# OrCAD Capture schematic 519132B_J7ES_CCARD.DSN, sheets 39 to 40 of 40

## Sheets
39 37.EXPANSION/GNSS: size C; rev: A
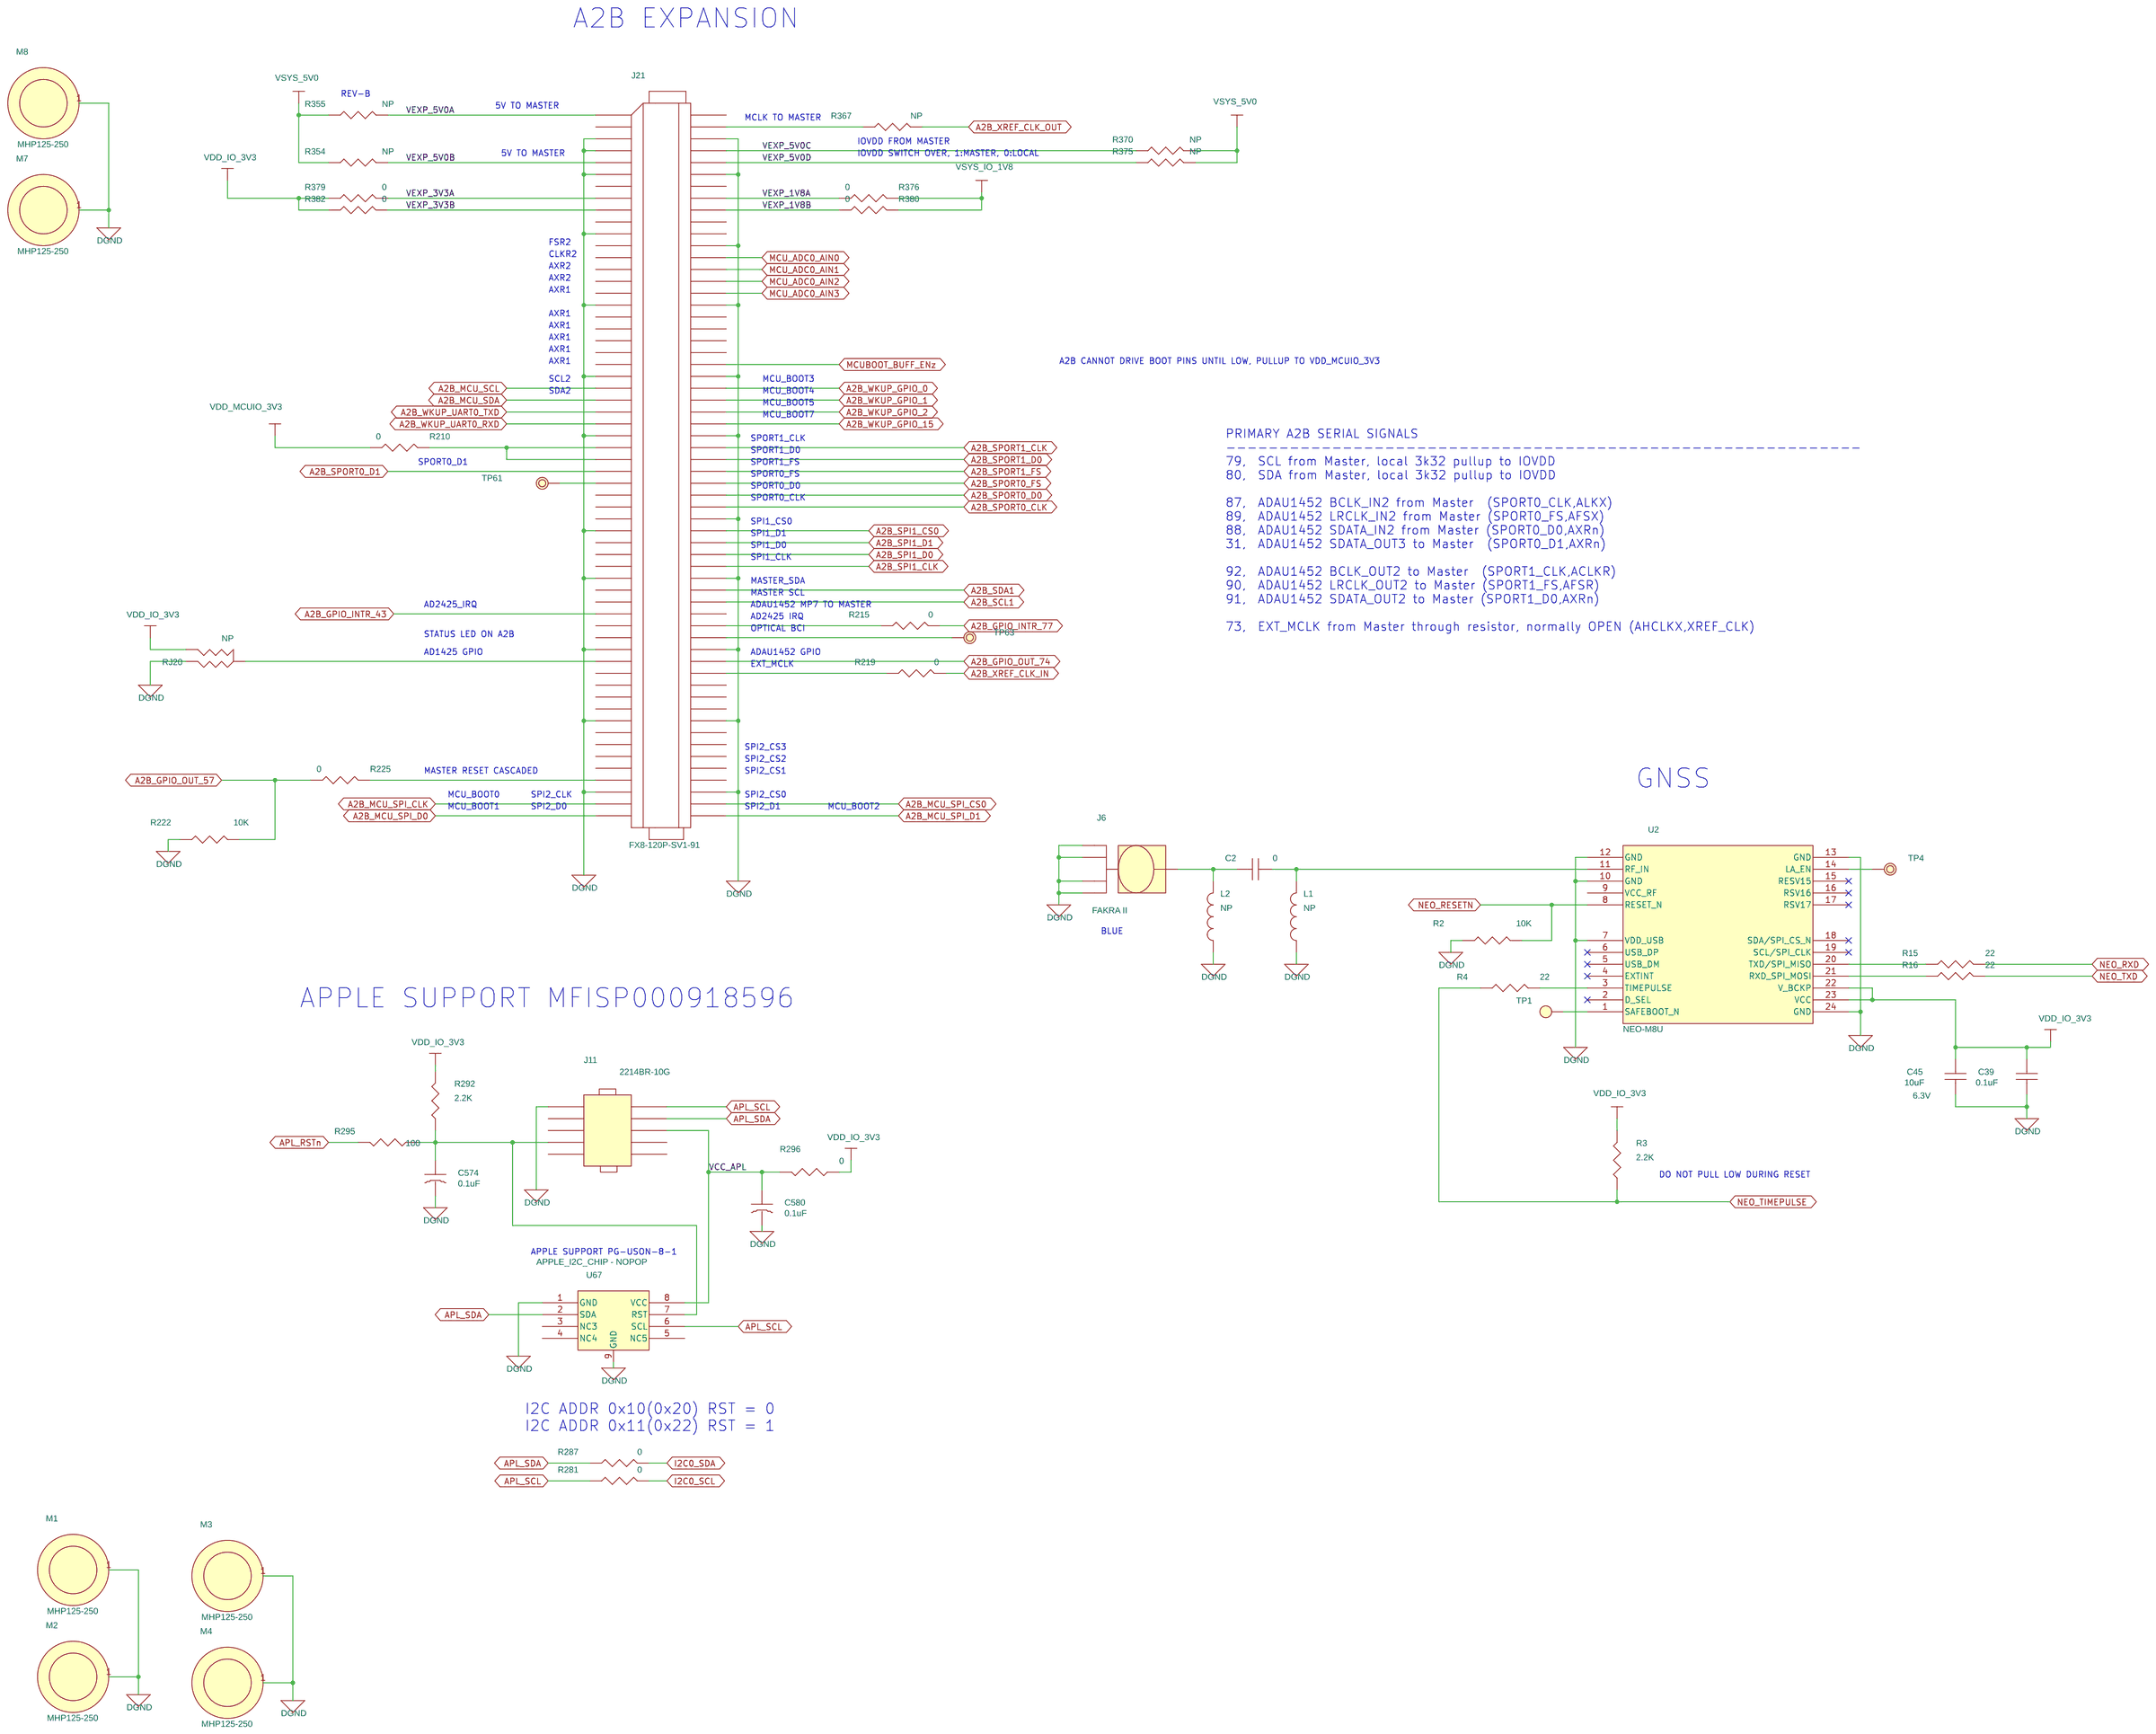
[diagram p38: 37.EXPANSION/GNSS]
40 26.SECONDARY LDO'S/SWITCHES: size C; rev: A
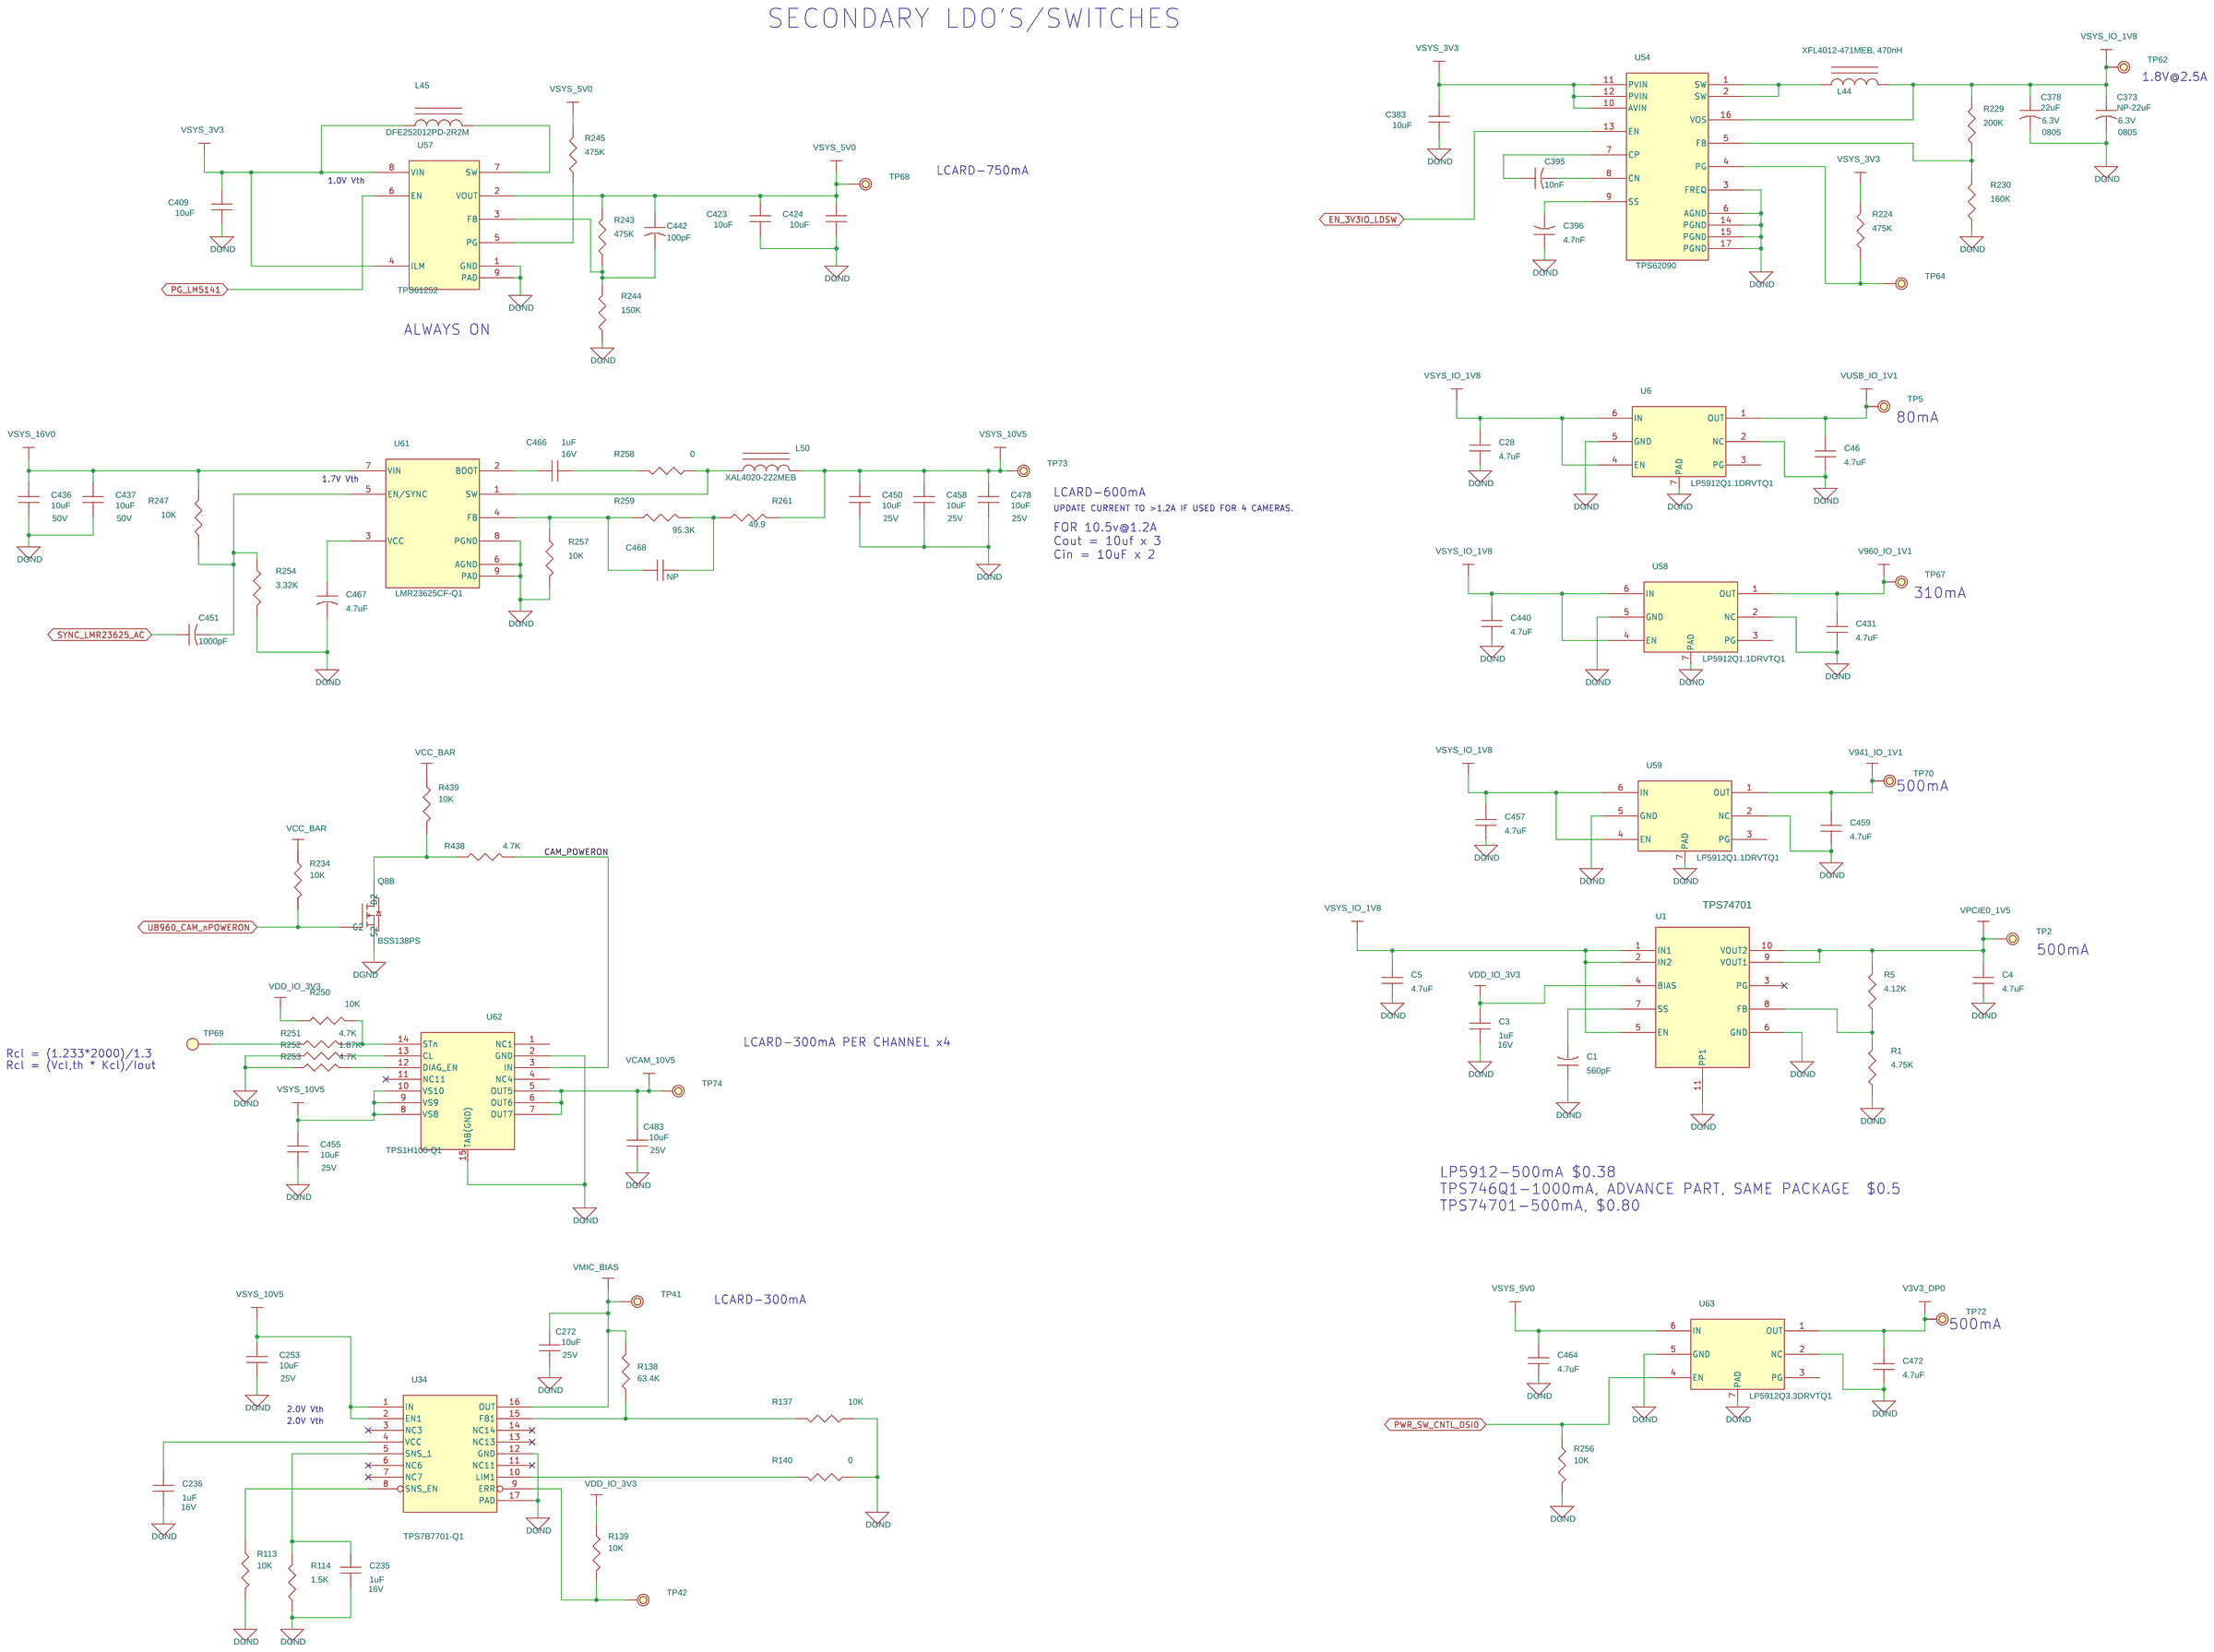
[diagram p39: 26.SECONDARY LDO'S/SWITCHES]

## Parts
sheet 14. SOC MCU & MAIN GEN IO, OSC
Q8  BSS138PS  [sot363-16x45]  (sections A,B)
sheet 26.SECONDARY LDO'S/SWITCHES
C1  560pF  [c402-25]
C3  1uF  [c603-35x45]
C4  4.7uF  [c805-35x60]
C5  4.7uF  [c805-35x60]
C28  4.7uF  [c805-35x60]
C46  4.7uF  [c805-35x60]
C235  1uF  [c603-35x45]
C236  1uF  [c603-35x45]
C253  10uF  [C1206-40X70]
C272  10uF  [C1206-40X70]
C373  NP-22uF  [c805-35x60]
C378  22uF  [c805-35x60]
C383  10uF  [c805-35x60]
C395  10nF  [c402-25]
C396  4.7nF  [c402-25]
C409  10uF  [c805-35x60]
C423  10uF  [c805-35x60]
C424  10uF  [c805-35x60]
C431  4.7uF  [c805-35x60]
C436  10uF  [c1210-70x102]
C437  10uF  [c1210-70x102]
C440  4.7uF  [c805-35x60]
C442  100pF  [c402-25]
C450  10uF  [C1206-40X70]
C451  1000pF  [c402-25]
C455  10uF  [C1206-40X70]
C457  4.7uF  [c805-35x60]
C458  10uF  [C1206-40X70]
C459  4.7uF  [c805-35x60]
C464  4.7uF  [c805-35x60]
C466  1uF  [c603-35x45]
C467  4.7uF  [c603-35x45]
C468  NP  [c402-25]
C472  4.7uF  [c805-35x60]
C478  10uF  [C1206-40X70]
C483  10uF  [C1206-40X70]
L44  XFL4012-471MEB, 470nH  [coil-xlf4012]
L45  DFE252012PD-2R2M  [ind2520-40x80]
L50  XAL4020-222MEB  [coil-xal40]
R1  4.75K  [r402-25]
R5  4.12K  [r402-25]
R113  10K  [r402-25]
R114  1.5K  [r402-25]
R137  10K  [r402-25]
R138  63.4K  [r402-25]
R139  10K  [r402-25]
R140  0  [r402-25]
R224  475K  [r402-25]
R229  200K  [r402-25]
R230  160K  [r402-25]
R234  10K  [r402-25]
R243  475K  [r402-25]
R244  150K  [r402-25]
R245  475K  [r402-25]
R247  10K  [r402-25]
R250  10K  [r402-25]
R251  4.7K  [r402-25]
R252  1.87K  [r603-35x45]
R253  4.7K  [r402-25]
R254  3.32K  [r402-25]
R256  10K  [r402-25]
R257  10K  [r402-25]
R258  0  [r402-25]
R259  95.3K  [r402-25]
R261  49.9  [r402-25]
R438  4.7K  [r402-25]
R439  10K  [r402-25]
TP2  TP  [tp-30RD13]
TP5  TP  [tp-30RD13]
TP41  TP  [tp-30RD13]
TP42  TP  [tp-30RD13]
TP62  TP  [tp-30RD13]
TP64  TP  [tp-30RD13]
TP67  TP  [tp-30RD13]
TP68  TP  [tp-30RD13]
TP69  NP  [tp20]
TP70  TP  [tp-30RD13]
TP72  TP  [tp-30RD13]
TP73  TP  [tp-30RD13]
TP74  TP  [tp-30RD13]
U1  TPS74701  [drc10-11x33]
U6  LP5912Q1.1DRVTQ1  [drv6-12x30]
U34  TPS7B7701-Q1  [pwp16-14x70-pad]
U54  TPS62090  [rgt16-12x34]
U57  TPS61252  [dsg8-11x20]
U58  LP5912Q1.1DRVTQ1  [drv6-12x30]
U59  LP5912Q1.1DRVTQ1  [drv6-12x30]
U61  LMR23625CF-Q1  [DDA8-PAD]
U62  TPS1H100-Q1  [pwp14-14x70-pad]
U63  LP5912Q3.3DRVTQ1  [drv6-12x30]
sheet 37.EXPANSION/GNSS
C2  0  [c402-25]
C39  0.1uF  [c402-25]
C45  10uF  [c805-35x60]
C574  0.1uF  [c402-25]
C580  0.1uF  [c402-25]
J6  FAKRA II  [conn-st-fakra]
J11  2214BR-10G  [CON-2214BR-10G]
J21  FX8-120P-SV1-91  [FX8-120P-SV1]
L1  NP  [l402-25]
L2  NP  [l402-25]
M1  MHP125-250  [MHP125-250]
M2  MHP125-250  [MHP125-250]
M3  MHP125-250  [MHP125-250]
M4  MHP125-250  [MHP125-250]
M7  MHP125-250  [MHP125-250]
M8  MHP125-250  [MHP125-250]
R2  10K  [r402-25]
R3  2.2K  [r402-25]
R4  22  [r402-25]
R15  22  [r402-25]
R16  22  [r402-25]
R210  0  [r402-25]
R215  0  [r402-25]
R219  0  [r402-25]
R222  10K  [r402-25]
R225  0  [r402-25]
R281  0  [r402-25]
R287  0  [r402-25]
R292  2.2K  [r402-25]
R295  100  [r402-25]
R296  0  [r402-25]
R354  NP  [r402-25]
R355  NP  [r402-25]
R367  NP  [r402-25]
R370  NP  [r402-25]
R375  NP  [r402-25]
R376  0  [r402-25]
R379  0  [r402-25]
R380  0  [r402-25]
R382  0  [r402-25]
RJ20  NP  [JMP402-25]
TP1  TP  [TP20]
TP4  TP  [tp-30RD13]
TP61  TP  [tp-30RD13]
TP63  TP  [tp-30RD13]
U2  NEO-M8U  [NEO-M8U]
U67  APPLE_I2C_CHIP - NOPOP  [IC8-CP-USON]

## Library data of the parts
Q8 = BSS138PS: Part #: 104958-0001R
C1 = CAP: CAP CERAMIC 0.01uF 50V 10% X7R 0402; Chkd/date: SHREESHAIL/301105; Crtd /date: MAZHAR/040505; Custom_Duty: 15%; Customs_HS_Code: 85322990; Distributor_name: DIGIKEY; Distributor_part_number: 399-3066-1-ND; Footprint Path: Y:\MIS_DATABASE\Library\ALTIUM_TOOL\PCB_FOOTPRINTS\Altium_Footprint_Lib.PcbLib; Height: 0.55MM; Library Path: Y:\MIS_DATABASE\Library\ALTIUM_TOOL\SCHEMATICS_PARTS\MS_DISCRETE_Library.schlib; Mfr_name: KEMET; Mfr_part_number: C0402C103K5RACTU; Mistral Part No: 120009030025-R; Package: 0402; Part #: 101587-5601R; Part_type: CAPACITORS\CERAMIC; Project: G4_SVGA; RoHS: RoHS; Temperature: -55°C+125°C; Tolerance: 10%; Voltage: 50V; Wattage: NA; Weight: 0.65mg; Datasheet: Y:\MIS_DATABASE\DATASHEETS\CAPACITORS\KEMET-C-X7R.PDF
C3 C235 C236 = CAP_NP_0: Part #: 104723-0100R; Voltage: 16V
C4 C5 C28 C46 C431 C440 C457 C459 C464 C472 = CAP_AM_0805_4.7uf_x7r_16v_10_X: Part #: 104719-0470R
C253 C272 C450 C455 C458 C478 C483 = CAP_NP_0: Part #: 104724-0101R; Voltage: 25V
C373 = CAP: CAP CERAMIC 22uF 6.3V 20% X7T AUTO 0805; Chkd/date: MANIRAJA/261018; Crtd /date: ALVY/251018; Custom_Duty: 15%; Customs_HS_Code: 85322990; Distributor_name: MOUSER; Distributor_part_number: 81-GCM21BD70J226ME6L; Footprint Path: Y:\MIS_DATABASE\Library\ALTIUM_TOOL\PCB_FOOTPRINTS\Altium_Footprint_Lib.PcbLib; Height: 1.25MM; Library Path: Y:\MIS_DATABASE\Library\ALTIUM_TOOL\SCHEMATICS_PARTS\MS_DISCRETE_Library.schlib; Mfr_name: MURATA; Mfr_part_number: GCM21BD70J226ME36L; Mistral Part No: 120018100065-R; Package: 0805; Part #: C0805-NOPOP; Part_type: CAPACITORS\CERAMIC; Project: TI_J7ES_EVM_SOM; RoHS: RoHS; Temperature: -55°C+125°C; Tolerance: 20%; Voltage: 6.3V; Wattage: NA; Weight: NA; Datasheet: Y:\MIS_DATABASE\DATASHEETS\CAPACITORS\GCM-SERIES.PDF
C378 = CAP: CAP CERAMIC 22uF 6.3V 20% X7T AUTO 0805; Chkd/date: MANIRAJA/261018; Crtd /date: ALVY/251018; Custom_Duty: 15%; Customs_HS_Code: 85322990; Distributor_name: MOUSER; Distributor_part_number: 81-GCM21BD70J226ME6L; Footprint Path: Y:\MIS_DATABASE\Library\ALTIUM_TOOL\PCB_FOOTPRINTS\Altium_Footprint_Lib.PcbLib; Height: 1.25MM; Library Path: Y:\MIS_DATABASE\Library\ALTIUM_TOOL\SCHEMATICS_PARTS\MS_DISCRETE_Library.schlib; Mfr_name: MURATA; Mfr_part_number: GCM21BD70J226ME36L; Mistral Part No: 120018100065-R; Package: 0805; Part #: 105333-0221R; Part_type: CAPACITORS\CERAMIC; Project: TI_J7ES_EVM_SOM; RoHS: RoHS; Temperature: -55°C+125°C; Tolerance: 20%; Voltage: 6.3V; Wattage: NA; Weight: NA; Datasheet: Y:\MIS_DATABASE\DATASHEETS\CAPACITORS\GCM-SERIES.PDF
C383 C409 C423 C424 = CAP_AM_0805_10uf_x7r_10v_10_X: Part #: 104720-0101R
C395 = CAP: CAP CERAMIC 0.01uF 50V 10% X7R 0402; Chkd/date: SHREESHAIL/301105; Crtd /date: MAZHAR/040505; Custom_Duty: 15%; Customs_HS_Code: 85322990; Distributor_name: DIGIKEY; Distributor_part_number: 399-3066-1-ND; Footprint Path: Y:\MIS_DATABASE\Library\ALTIUM_TOOL\PCB_FOOTPRINTS\Altium_Footprint_Lib.PcbLib; Height: 0.55MM; Library Path: Y:\MIS_DATABASE\Library\ALTIUM_TOOL\SCHEMATICS_PARTS\MS_DISCRETE_Library.schlib; Mfr_name: KEMET; Mfr_part_number: C0402C103K5RACTU; Mistral Part No: 120009030025-R; Package: 0402; Part #: 104725-1101R; Part_type: CAPACITORS\CERAMIC; Project: G4_SVGA; RoHS: RoHS; Temperature: -55°C+125°C; Tolerance: 10%; Voltage: 50V; Wattage: NA; Weight: 0.65mg; Datasheet: Y:\MIS_DATABASE\DATASHEETS\CAPACITORS\KEMET-C-X7R.PDF
C396 = CAP: CAP CERAMIC 0.01uF 50V 10% X7R 0402; Chkd/date: SHREESHAIL/301105; Crtd /date: MAZHAR/040505; Custom_Duty: 15%; Customs_HS_Code: 85322990; Distributor_name: DIGIKEY; Distributor_part_number: 399-3066-1-ND; Footprint Path: Y:\MIS_DATABASE\Library\ALTIUM_TOOL\PCB_FOOTPRINTS\Altium_Footprint_Lib.PcbLib; Height: 0.55MM; Library Path: Y:\MIS_DATABASE\Library\ALTIUM_TOOL\SCHEMATICS_PARTS\MS_DISCRETE_Library.schlib; Mfr_name: KEMET; Mfr_part_number: C0402C103K5RACTU; Mistral Part No: 120009030025-R; Package: 0402; Part #: 103217-1472R; Part_type: CAPACITORS\CERAMIC; Project: G4_SVGA; RoHS: RoHS; Temperature: -55°C+125°C; Tolerance: 10%; Voltage: 25V; Wattage: NA; Weight: 0.65mg; Datasheet: Y:\MIS_DATABASE\DATASHEETS\CAPACITORS\KEMET-C-X7R.PDF
C436 C437 = CAP_NP_0: Part #: 104665-0101R; Voltage: 50V
C442 = CAP: Part #: 101782-1103R; Voltage: 50V
C451 = CAP: CAP CERAMIC 0.01uF 50V 10% X7R 0402; Chkd/date: SHREESHAIL/301105; Crtd /date: MAZHAR/040505; Custom_Duty: 15%; Customs_HS_Code: 85322990; Distributor_name: DIGIKEY; Distributor_part_number: 399-3066-1-ND; Footprint Path: Y:\MIS_DATABASE\Library\ALTIUM_TOOL\PCB_FOOTPRINTS\Altium_Footprint_Lib.PcbLib; Height: 0.55MM; Library Path: Y:\MIS_DATABASE\Library\ALTIUM_TOOL\SCHEMATICS_PARTS\MS_DISCRETE_Library.schlib; Mfr_name: KEMET; Mfr_part_number: C0402C103K5RACTU; Mistral Part No: 120009030025-R; Package: 0402; Part #: 102058-1102R; Part_type: CAPACITORS\CERAMIC; Project: G4_SVGA; RoHS: RoHS; Temperature: -55°C+125°C; Tolerance: 10%; Voltage: 50V; Wattage: NA; Weight: 0.65mg; Datasheet: Y:\MIS_DATABASE\DATASHEETS\CAPACITORS\KEMET-C-X7R.PDF
C466 = CAP_AM_0603_0.47uf_x7r_16v_10_X: Part #: 104723-0100R; Voltage: 16V
C467 = CAP: Part #: 104938-0470R; Voltage: 6.3V
C468 = CAP_AM_0402_0.1uf_x7r_16v_10%_X: Part #: C0402-NOPOP; Voltage: 50V
L44 = INDUCTOR_IRON: Part #: 105285-1470R
L45 = INDUCTOR_IRON: Part #: 104717-0220R
L50 = INDUCTOR_IRON: Part #: 104872-0220R
R1 = R: Part #: 102145-4752R
R5 = R: Part #: 102145-4122R
R2 R113 R137 R139 R222 R234 R247 R256 R439 = R: Part #: 102145-1003R
R114 = R: Part #: 102145-1502R
R138 = R: Part #: 102145-6343R
R140 R210 R215 R219 R225 R258 R281 R287 R296 R376 R379 R380 R382 = R: Part #: 101370-0001R
R224 R243 R245 = R: Part #: 102145-4754R
R229 = R: Part #: 102145-2004R
R230 = R: Part #: 102145-1604R
R244 = R: Part #: 102145-1504R
R250 = R_1: Part #: 102145-1003R
R251 R253 R438 = R_2: Part #: 102145-4702R
R252 = R_2: Part #: 100642-1872R
R254 = R: Part #: 102145-3322R
R257 = RESISTOR: Part #: 102145-1003R
R259 = RESISTOR: Part #: 102145-9533R
R261 = RESISTOR: Part #: 102145-4990R
TP2 TP4 TP5 TP41 TP42 TP61-TP64 TP67 TP68 TP70 TP72-TP74 = TP-30RD13: Part #: TP-30RD13-NO-POP
TP1 TP69 = TESTPOINT: Part #: SMT-TP020
U1 = U-TPS78601_AJUST_-_1_3.5A_LDO: Part #: 102752-0001R
U6 U58 U59 = LP5912-Q1: Part #: 105194-0011R
U34 = TPS7B7701-Q1: Part #: 104921-0001R
U54 = TPS62090: Part #: 105344-0001R
U57 = TPS61252: Part #: 104960-0001R
U61 = LMR23625CF-Q1: Part #: 104967-0001R
U62 = tps1h100-q1: Part #: 104666-0001R
U63 = LP5912-Q1: Part #: 105194-0033R
C2 = CAP_NP_3: Alternate_mfr_part_number_B: 102366-1685R; Part #: 101370-0001R
C39 = CAP_AM_0402_0.1uf_x7r_16v_10%_X: Part #: 104446-1100R
C45 = CAP_AM_0805_4.7uf_x7r_16v_10_X: Part #: 104936-0101R; Voltage: 6.3V
C574 C580 = CAP: Part #: 104446-1100R; Voltage: 16V
J6 = 59S20X-400L5-Z: Part #: 104894-0003R
J11 = HEADER_5X2: Part #: 105017-0010R
J21 = FX8-120P-SV1-91: Part #: 104890-0120R
L1 L2 = INDUCTOR: Part #: L0402-NOPOP
M1-M4 M7 M8 = MHP125-250: Part #: NOPOP
R3 R292 = R: Part #: 102145-2202R
R4 R15 R16 = R: Part #: 101370-2200R
R295 = R: Part #: 102145-1001R
R354 R355 R367 R370 R375 = R: Part #: R0402-NOPOP
RJ20 = RJUMP3: Part #: NOPOP
U2 = NEO-M8U: Part #: 104902-0001R
U67 = APPLE_I2C_CHIP: Part #: NOPOP

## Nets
DGND: C1.1 C3.2 C4.1 C5.1 C28.1 C39.2 C45.2 C46.1 C235.2 C236.2 C253.2 C272.2 C373.2 C378.2 C383.2 C396.1 C409.2 C423.2 C424.2 C431.1 C436.2 C437.2 C440.1 C450.2 C455.2 C457.1 C458.2 C459.1 C464.1 C467.2 C472.1 C478.2 C483.2 C574.2 C580.2 J6.2 J6.3 J6.4 J6.5 J11.2 J21.3 J21.4 J21.6 J21.11 J21.17 J21.23 J21.28 J21.36 J21.40 J21.46 J21.52 J21.58 J21.63 J21.69 J21.75 J21.81 J21.86 J21.93 J21.98 J21.104 J21.109 J21.115 J21.118 L1.1 L2.1 M1.1 M2.1 M3.1 M4.1 M7.1 M8.1 Q8.4(S2) R1.1 R2.1 R113.2 R114.2 R137.2 R140.2 R222.1 R230.1 R244.1 R252.1 R253.1 R254.2 R256.2 R257.2 RJ20.1 U1.6(GND) U1.11(PP1) U2.7(VDD_USB) U2.10(GND) U2.12(GND) U2.13(GND) U2.24(GND) U6.2(NC) U6.5(GND) U6.7(PAD) U34.12(GND) U34.17(PAD) U54.3(FREQ) U54.6(AGND) U54.14(PGND) U54.15(PGND) U54.17(PGND) U57.1(GND) U57.9(PAD) U58.2(NC) U58.5(GND) U58.7(PAD) U59.2(NC) U59.5(GND) U59.7(PAD) U61.6(AGND) U61.8(PGND) U61.9(PAD) U62.2(GND) U62.15(TAB(GND)) U63.2(NC) U63.5(GND) U63.7(PAD) U67.1(GND) U67.9(GND) ; also on sheet 8 9 10 11 12 13 14 15 17 18 19 20 21 22 23 24 25 26 27 28 29 30 31 32 33 34 35 36 37 38
V3V3_DP0: C472.2 TP72.1(TP) U63.1(OUT) ; also on sheet 29
V941_IO_1V1: C459.2 TP70.1(TP) U59.1(OUT) ; also on sheet 30
V960_IO_1V1: C431.2 TP67.1(TP) U58.1(OUT) ; also on sheet 31
VCC_APL: C580.1 J11.5 R296.2 U67.8(VCC)
VDD_IO_3V3: C3.1 C39.1 C45.1 R3.1 R139.1 R234.1 R250.1 R292.2 R296.1 R379.2 R382.2 R439.1 RJ20.3 U1.4(BIAS) U2.22(V_BCKP) U2.23(VCC) ; also on sheet 10 15 16 18 21 25 26 27 28 29 30 31 32 34 35 36 37 38
VDD_MCUIO_3V3: R210.2 ; also on sheet 14 18 23 24 25 26 34 37
A2B_GPIO_INTR_43: J21.43 ; also on sheet 16
A2B_GPIO_INTR_77: R215.2 ; also on sheet 16
A2B_GPIO_OUT_57: R222.2 R225.2 ; also on sheet 16
A2B_GPIO_OUT_74: J21.74 ; also on sheet 16
A2B_MCU_SCL: J21.24 ; also on sheet 14
A2B_MCU_SDA: J21.25 ; also on sheet 14
A2B_MCU_SPI_CLK: J21.59 ; also on sheet 14 26
A2B_MCU_SPI_CS0: J21.62 ; also on sheet 14
A2B_MCU_SPI_D0: J21.60 ; also on sheet 14 26
A2B_MCU_SPI_D1: J21.61 ; also on sheet 14 26
A2B_SCL1: J21.79 ; also on sheet 10
A2B_SDA1: J21.80 ; also on sheet 10
A2B_SPI1_CLK: J21.82 ; also on sheet 13
A2B_SPI1_CS0: J21.85 ; also on sheet 13
A2B_SPI1_D0: J21.83 ; also on sheet 13
A2B_SPI1_D1: J21.84 ; also on sheet 13
A2B_SPORT0_CLK: J21.87 ; also on sheet 16
A2B_SPORT0_D0: J21.88 ; also on sheet 16
A2B_SPORT0_D1: J21.31 ; also on sheet 16
A2B_SPORT0_FS: J21.89 ; also on sheet 16
A2B_SPORT1_CLK: J21.92 ; also on sheet 16
A2B_SPORT1_D0: J21.91 ; also on sheet 16
A2B_SPORT1_FS: J21.90 ; also on sheet 16
A2B_WKUP_GPIO_0: J21.97 ; also on sheet 14 26
A2B_WKUP_GPIO_1: J21.96 ; also on sheet 14 26
A2B_WKUP_GPIO_2: J21.95 ; also on sheet 14 26
A2B_WKUP_GPIO_15: J21.94 ; also on sheet 14 26
A2B_WKUP_UART0_RXD: J21.27 ; also on sheet 14
A2B_WKUP_UART0_TXD: J21.26 ; also on sheet 14
A2B_XREF_CLK_IN: R219.2 ; also on sheet 13
A2B_XREF_CLK_OUT: R367.2 ; also on sheet 13
APL_RSTn: R295.1 ; also on sheet 15
APL_SCL: J11.1 R281.1 U67.6(SCL)
APL_SDA: J11.3 R287.1 U67.2(SDA)
CAM_POWERON: R438.2 U62.3(IN)
EN_3V3IO_LDSW: U54.13(EN) ; also on sheet 21 24 25 34
I2C0_SCL: R281.2 ; also on sheet 15
I2C0_SDA: R287.2 ; also on sheet 15
MCU_ADC0_AIN0: J21.108 ; also on sheet 13
MCU_ADC0_AIN1: J21.107 ; also on sheet 13
MCU_ADC0_AIN2: J21.106 ; also on sheet 13
MCU_ADC0_AIN3: J21.105 ; also on sheet 13
MCU_DMTIMER5: C451.1 ; also on sheet 13
MCUBOOT_BUFF_ENz: J21.99 ; also on sheet 14 22 34
NEO_RESETN: R2.2 U2.8(RESET_N) ; also on sheet 15
NEO_RXD: R15.2 ; also on sheet 15
NEO_TIMEPULSE: R3.2 R4.1 ; also on sheet 10
NEO_TXD: R16.2 ; also on sheet 15
PG_LM5141: U57.6(EN) ; also on sheet 22 23
PWR_SW_CNTL_DSI0: R256.1 U63.4(EN) ; also on sheet 15
UB960_CAM_nPOWERON: Q8.5(G2) R234.2 ; also on sheet 15
VCAM_10V5: C483.1 TP74.1(TP) U62.5(OUT5) U62.6(OUT6) U62.7(OUT7) ; also on sheet 31
VEXP_1V8A: J21.113 R376.2
VEXP_1V8B: J21.112 R380.2
VEXP_3V3A: J21.8 R379.1
VEXP_3V3B: J21.9 R382.1
VEXP_5V0A: J21.1 R355.1
VEXP_5V0B: J21.5 R354.1
VEXP_5V0C: J21.117 R370.2
VEXP_5V0D: J21.116 R375.2
VMIC_BIAS: C272.1 R138.1 TP41.1(TP) U34.16(OUT) ; also on sheet 33
VPCIE0_1V5: C4.2 R5.2 TP2.1(TP) U1.9(VOUT1) U1.10(VOUT2) ; also on sheet 38
VSYS_3V3: C383.1 C409.1 L45.1 R224.2 U54.10(AVIN) U54.11(PVIN) U54.12(PVIN) U57.4(ILM) U57.8(VIN) ; also on sheet 17 22 23 25 34
VSYS_5V0: C423.1 C424.1 C442.1 C464.2 R243.2 R245.2 R354.2 R355.2 R370.1 R375.1 TP68.1(TP) U57.2(VOUT) U63.6(IN) ; also on sheet 22 37
VSYS_10V5: C253.1 C450.1 C455.1 C458.1 C478.1 L50.2 R261.2 TP73.1(TP) U34.1(IN) U34.2(EN1) U62.8(VS8) U62.9(VS9) U62.10(VS10) ; also on sheet 21
VSYS_16V0: C436.1 C437.1 R247.1 U61.7(VIN) ; also on sheet 21 22
VSYS_IO_1V8: C5.2 C28.2 C373.1 C378.1 C440.2 C457.2 L44.2 R229.2 R376.1 R380.1 TP62.1(TP) U1.1(IN1) U1.2(IN2) U1.5(EN) U6.4(EN) U6.6(IN) U54.16(VOS) U58.4(EN) U58.6(IN) U59.4(EN) U59.6(IN) ; also on sheet 30 31 35
VUSB_IO_1V1: C46.2 TP5.1(TP) U6.1(OUT) ; also on sheet 38
N29159706: C574.1 J11.8 R292.1 R295.2 U67.7(RST)
N29176310: J21.119 R367.1
N29176636: J21.32 TP61.1(TP)
N29176758: J21.77 R215.1
N29176776: J21.76 TP63.1(TP)
N29176797: J21.47 RJ20.2
N29176814: J21.73 R219.1
N29176862: J21.57 R225.1
N29214431: C2.2 J6.1 L2.2
N29214437: C2.1 L1.2 U2.11(RF_IN)
N29214443: TP4.1(TP) U2.14(LA_EN)
N29214525: R15.1 U2.20(TXD/SPI_MISO)
N29214549: R16.1 U2.21(RXD_SPI_MOSI)
N29214557: R4.2 U2.3(TIMEPULSE)
N29214575: TP1.1(TP) U2.1(SAFEBOOT_N)
N29626619: C236.1 U34.4(VCC)
N29626723: R137.1 R138.2 U34.15(FB1)
N29626795: C235.1 R114.1 U34.5(SNS_1)
N29626827: R140.1 U34.10(LIM1)
N29626839: R113.1 U34.8(SNS_EN)
N29626843: R139.2 TP42.1(TP) U34.9(ERR)
N30130836: R250.2 R251.2 U62.14(STn)
N30130873: R251.1 TP69.1(TP)
N30130899: R252.2 U62.13(CL)
N30130913: R253.2 U62.12(DIAG_EN)
N30133146: Q8.3(D2) R438.1 R439.2
N30808408: L45.2 U57.7(SW)
N30809211: C442.2 R243.1 R244.2 U57.3(FB)
N30811250: C451.2 R247.2 R254.1 U61.5(EN/SYNC)
N30811520: C467.1 U61.3(VCC)
N30812987: C466.1 U61.2(BOOT)
N30812990: C466.2 R258.1
N30812993: L50.1 R258.2 U61.1(SW)
N30813342: C468.1 R257.1 R259.1 U61.4(FB)
N30813649: C468.2 R259.2 R261.1
N30821669: R245.1 U57.5(PG)
N31823309: R224.1 TP64.1(TP) U54.4(PG)
N31823321: R229.1 R230.2 U54.5(FB)
N31823861: L44.1 U54.1(SW) U54.2(SW)
N31828740: C395.1 U54.7(CP)
N31828749: C395.2 U54.8(CN)
N31829052: C396.2 U54.9(SS)
N31832097: R1.2 R5.1 U1.8(FB)
N31834422: C1.2 U1.7(SS)
N32011520: J21.29 J21.30 R210.1

Not connected (* = marked no-connect by the designer): J11 4 6 7 9 10; J21 2 7 10 12 13 14 15 16 18 19 20 21 22 33 34 35 37 38 39 41 42 44 45 48 49 50 51 53 54 55 56 64 65 66 67 68 70 71 72 78 100 101 102 103 110 111 114 120; U1 3(PG)*; U2 2(D_SEL)* 4(EXTINT)* 5(USB_DM)* 6(USB_DP)* 9(VCC_RF) 15(RESV15)* 16(RSV16)* 17(RSV17)* 18(SDA/SPI_CS_N)* 19(SCL/SPI_CLK)*; U6 3(PG); U34 3(NC3)* 6(NC6)* 7(NC7)* 11(NC11)* 13(NC13)* 14(NC14)*; U58 3(PG); U59 3(PG); U62 1(NC1) 4(NC4) 11(NC11)*; U63 3(PG); U67 3(NC3) 4(NC4) 5(NC5)

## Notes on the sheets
sheet 39
- A2B EXPANSION
- REV-B
- 5V TO MASTER
- MCLK TO MASTER
- IOVDD FROM MASTER
- 5V TO MASTER
- IOVDD SWITCH OVER, 1:MASTER, 0:LOCAL
- FSR2
- CLKR2
- AXR2
- AXR1
- AXR2
- AXR1
- AXR1
- AXR1
- AXR1
- AXR1
- A2B CANNOT DRIVE BOOT PINS UNTIL LOW, PULLUP TO VDD_MCUIO_3V3
- SCL2
- MCU_BOOT3
- SDA2
- MCU_BOOT4
- MCU_BOOT5
- MCU_BOOT7
- SPORT1_CLK
- PRIMARY A2B SERIAL SIGNALS
  ------------------------------------------------------------
  79,	SCL from Master, local 3k32 pullup to IOVDD
  80,	SDA from Master, local 3k32 pullup to IOVDD
  87,	ADAU1452 BCLK_IN2 from Master  (SPORT0_CLK,ALKX)
  89,	ADAU1452 LRCLK_IN2 from Master (SPORT0_FS,AFSX)
  88,	ADAU1452 SDATA_IN2 from Master (SPORT0_D0,AXRn)
  31,	ADAU1452 SDATA_OUT3 to Master  (SPORT0_D1,AXRn)
  92,	ADAU1452 BCLK_OUT2 to Master  (SPORT1_CLK,ACLKR)
  90,	ADAU1452 LRCLK_OUT2 to Master (SPORT1_FS,AFSR)
  91,	ADAU1452 SDATA_OUT2 to Master (SPORT1_D0,AXRn)
  73,	EXT_MCLK from Master through resistor, normally OPEN (AHCLKX,XREF_CLK)
- SPORT1_D0
- SPORT0_D1
- SPORT1_FS
- SPORT0_D0
- SPORT0_FS
- SPORT0_CLK
- SPI1_CS0
- SPI1_D1
- SPI1_CLK
- SPI1_D0
- MASTER_SDA
- MASTER SCL
- AD2425_IRQ
- ADAU1452 MP7 TO MASTER
- AD2425 IRQ
- STATUS LED ON A2B
- OPTICAL BCI
- AD1425 GPIO
- ADAU1452 GPIO
- EXT_MCLK
- SPI2_CS3
- SPI2_CS2
- MASTER RESET CASCADED
- SPI2_CS1
- GNSS
- MCU_BOOT0
- SPI2_CLK
- SPI2_CS0
- MCU_BOOT1
- SPI2_D0
- SPI2_D1
- MCU_BOOT2
- BLUE
- APPLE SUPPORT MFISP000918596
- DO NOT PULL LOW DURING RESET
- APPLE SUPPORT PG-USON-8-1
- I2C ADDR 0x10(0x20) RST = 0
  I2C ADDR 0x11(0x22) RST = 1
sheet 40
- SECONDARY LDO'S/SWITCHES
- 1.8V@2.5A
- LCARD-750mA
- 1.0V Vth
- ALWAYS ON
- 80mA
- 1.7V Vth
- LCARD-600mA
- UPDATE CURRENT TO >1.2A IF USED FOR 4 CAMERAS.
- FOR 10.5v@1.2A
  Cout = 10uf x 3
  Cin = 10uF x 2
- 310mA
- 500mA
- 500mA
- LCARD-300mA PER CHANNEL x4
- Rcl = (1.233*2000)/1.3
- Rcl = (Vcl,th * Kcl)/Iout
- LP5912-500mA $0.38
  TPS746Q1-1000mA, ADVANCE PART, SAME PACKAGE  $0.5
  TPS74701-500mA, $0.80
- LCARD-300mA
- 500mA
- 2.0V Vth
- 2.0V Vth
